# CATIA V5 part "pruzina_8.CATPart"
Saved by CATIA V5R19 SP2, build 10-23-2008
Part number: Pruzina delka 15mm
Bounding box of the stored display mesh (mm): x -8 to 8, y -8 to 8, z 0 to 15
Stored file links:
  D:\DURATEC\pruzina_8.CATPart
  D:\DURATEC\pruzina_1.CATPart
  D:\DURATEC\Pohyb pruziny.CATProduct
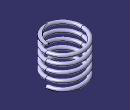
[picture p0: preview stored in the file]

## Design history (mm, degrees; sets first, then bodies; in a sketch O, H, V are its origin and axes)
External parameters (linked from other documents)
  `External.Delka pruziny` = 15 mm
  `External.Pocet zavitu` = 5
  `External.Vnitrni prumer pruziny` = 13 mm
  `External.Prumer dratu` = 1.5 mm
Set1
  Plane1: type Normal, Curve {line type PtDir, Direction (0, 0, 1), Start 0, End 15 {= `External.Delka pruziny`}, RefPoint {point type Coord, X 0, Y 0, Z 0}}, RefPoint vertex of Plane1
  Sketch1 on zx-plane, origin (0, 0, 0), H (-1, 0, 0), V (0, 0, 1)
    line L1 (6.5, 14) -> (6.5, 9)
    construction line L2 (6.5, 9) -> (-6.5, 9)
    line L3 (-6.5, 9) -> (-6.5, 14)
    construction line L4 (-6.5, 14) -> (6.5, 14)
    reference intersected line E1 through (0, 15) direction (-1, 0) from Plane1
    distance L3 L1 = 13 {= `External.Vnitrni prumer pruziny`}
    length L1 = 5
    distance L4 E1 = 1
    vertical: L1 V, L3 V
    horizontal: L2 H, L4 H
    equidistance: L1 L3 O
  Line1: type PtDir, Direction (0, 0, 1), Start 0, End 15 {= `External.Delka pruziny`}, RefPoint {point type Coord, X 0, Y 0, Z 0}
Body1 "Pruzina" (main body)
  Helix1: Pitch 3 {= `External.Delka pruziny` /`External.Pocet zavitu`}, TaperAngle 0, Height 15 {= Plane1.End}, Direction {line type PtDir, Direction (0, 0, 1), Start 0, End 15 {= `External.Delka pruziny`}, RefPoint {point type Coord, X 0, Y 0, Z 0}}, RefPoint {point type Coord, X 7.25 {= `External.Vnitrni prumer pruziny` /2+`External.Prumer dratu` /2}, Y 0, Z 0}
  Sketch2 on zx-plane, origin (0, 0, 0), H (-1, 0, 0), V (0, 0, 1)
    circle A1 centre (-7.25, 0) radius 0.75
    point P1 (-7.25, 0)
    reference projected point E1 (-7.25, 0) from vertex of Helix1
    radius A1 = 0.75 {= `External.Prumer dratu` /2}
    distance V A1 = 6.5 (reference)
    distance V A1 = 8 (reference)
    coincidence: P1 E1
  Rib1: profile Sketch2, centre curve Helix1
  Split1: SplitPlane xy-plane
  Split2: SplitPlane Plane1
